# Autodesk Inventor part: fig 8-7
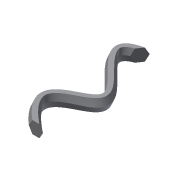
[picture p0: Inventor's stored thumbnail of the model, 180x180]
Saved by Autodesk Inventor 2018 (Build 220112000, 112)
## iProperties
Created: 2006-01
Part Number: fig 8-7
Document SubType Name: Modeling
Designer: CADCIM
Density: 1 g/cm^3
Material: Generic
Appearance: Default
Author: CADCIM
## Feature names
1. Sweep4
## Parameters: d3 = 0, d4 = 0
